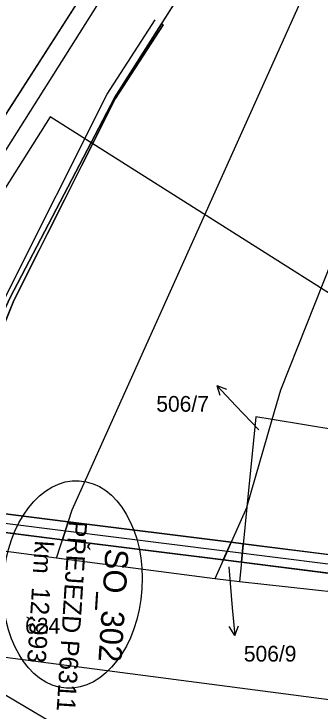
# Model space of a CAD drawing. Extents: x -746176 to -739709, y -1128407 to -1124482.
# Drawn here: x -743147.3 to -743114.2, y -1127113.5 to -1127038.1 of the extents above; entities that cross this region are included whole.
import ezdxf

# ---------------------------------------------------------------- set-up
doc = ezdxf.new("R2010")
doc.units = 0
for name, color, linetype in [('Vrstva 18', 7, 'Continuous'), ('Vrstva 21', 7, 'Continuous'), ('Vrstva 23', 7, 'Continuous'), ('Vrstva 29', 7, 'Continuous'), ('Vrstva 30', 7, 'Continuous'), ('Vrstva 31', 7, 'Continuous'), ('Vrstva 32', 7, 'Continuous'), ('Vrstva 33', 7, 'Continuous'), ('Vrstva 42', 7, 'Continuous'), ('Vrstva 43', 7, 'Continuous'), ('Vrstva 5', 7, 'Continuous'), ('Vrstva 6', 7, 'Continuous')]:
    doc.layers.add(name, color=color, linetype=linetype)

msp = doc.modelspace()

# ---------------------------------------------------------------- linework, layer by layer
at = {"layer": 'Vrstva 18'}
msp.add_lwpolyline([(-743072.487, -1126932.751), (-743098.647, -1126974.146), (-743125.94, -1127017.384), (-743152.604, -1127059.608), (-743175.023, -1127095.116), (-743199.163, -1127133.346), (-743215.971, -1127159.941), (-743232.818, -1127186.515), (-743247.456, -1127209.811), (-743254.52, -1127221.639), (-743261.299, -1127233.691), (-743264.155, -1127239.195), (-743264.862, -1127241.108), (-743267.337, -1127245.816), (-743268.289, -1127247.159), (-743271.711, -1127253.75), (-743281.122, -1127274.196), (-743291.923, -1127301.42), (-743296.724, -1127315.222), (-743301.116, -1127329.128), (-743306.787, -1127349.506)], dxfattribs=at)
at = {"layer": 'Vrstva 21'}
for p, q in [((-743136.47, -1127047.12), (-743131.381, -1127039.118)), ((-743131.226, -1127039.217), (-743136.391, -1127047.252)), ((-743131.381, -1127039.118), (-743131.226, -1127039.217)), ((-743147.78, -1127068.8), (-743136.47, -1127047.12)), ((-743136.391, -1127047.252), (-743147.347, -1127069.067)), ((-743147.347, -1127069.067), (-743151.792, -1127079.926)), ((-743149.573, -1127092.002), (-743141.471, -1127093.022)), ((-743141.471, -1127093.022), (-743142.103, -1127094.958)), ((-743141.471, -1127093.022), (-743123.858, -1127095.239)), ((-743142.103, -1127094.958), (-743150.442, -1127093.908)), ((-743124.702, -1127097.149), (-743142.103, -1127094.958)), ((-743123.858, -1127095.239), (-743124.702, -1127097.149)), ((-743123.858, -1127095.239), (-743122.548, -1127095.404)), ((-743122.548, -1127095.404), (-743122.742, -1127097.395)), ((-743122.548, -1127095.404), (-743105.198, -1127097.588)), ((-743122.742, -1127097.395), (-743124.702, -1127097.149)), ((-743105.47, -1127099.57), (-743122.742, -1127097.395))]:
    msp.add_line(p, q, dxfattribs=at)
at = {"layer": 'Vrstva 23'}
for points in [[(-743153.07, -1127080.408), (-743148.258, -1127068.653), (-743137.261, -1127046.755), (-743132.067, -1127038.676)], [(-743154.255, -1127082.611), (-743159.254, -1127091.791), (-743078.983, -1127101.896), (-743017.042, -1127110.608), (-742993.931, -1127114.824), (-742964.817, -1127120.763), (-742937.743, -1127126.541), (-742940.646, -1127140.696), (-742942.997, -1127146.397)]]:
    msp.add_lwpolyline(points, dxfattribs=at)
at = {"layer": 'Vrstva 29'}
msp.add_lwpolyline([(-743143.427, -1127049.192), (-743169.53, -1127090.542)], dxfattribs=at)
at = {"layer": 'Vrstva 30'}
for p, q in [((-743085.997, -1127085.593), (-743143.427, -1127049.192)), ((-743129.509, -1127122.8), (-743175.485, -1127095.847))]:
    msp.add_line(p, q, dxfattribs=at)
at = {"layer": 'Vrstva 31'}
msp.add_ellipse((-743140.999, -1127099.794), major_axis=(0.716, 11.227), ratio=0.666667, dxfattribs=at)
at = {"layer": 'Vrstva 33'}
for p, q in [((-743122.16, -1127091.42), (-743119.42, -1127081.96)), ((-743100.51, -1127085.04), (-743119.42, -1127081.96)), ((-743122.16, -1127091.42), (-743125.61, -1127099.18)), ((-743122.16, -1127091.42), (-743122.95, -1127099.53)), ((-743125.61, -1127099.18), (-743142.75, -1127096.94)), ((-743122.95, -1127099.53), (-743125.61, -1127099.18)), ((-743105.44, -1127101.41), (-743122.95, -1127099.53)), ((-743171.62, -1127104.6), (-743100.85, -1127113.88))]:
    msp.add_line(p, q, dxfattribs=at)
for points in [[(-743080.97, -1126930.41), (-743108.67, -1126985.4), (-743124.8, -1127012.28), (-743175.35, -1127091.16), (-743178.51, -1127091.81)], [(-743119.42, -1127081.96), (-743118.49, -1127078.74), (-743112.93, -1127064.74), (-743067.57, -1126961.77), (-743055.18, -1126936.67)], [(-743159.64, -1127094.74), (-743147.78, -1127068.8), (-743136.47, -1127047.12), (-743093.1, -1126978.92), (-743082.27, -1126962.07)], [(-743142.75, -1127096.94), (-743141.05, -1127091.73), (-743109, -1127020.35), (-743082.27, -1126962.07)], [(-743119.42, -1127081.96), (-743121.21, -1127081.67), (-743122.16, -1127091.42)], [(-743142.75, -1127096.94), (-743159.38, -1127094.77), (-743159.64, -1127094.74)]]:
    msp.add_lwpolyline(points, dxfattribs=at)
at = {"layer": 'Vrstva 43'}
for p, q in [((-743123.35, -1127080.45), (-743125.397, -1127078.255)), ((-743125.397, -1127078.255), (-743124.347, -1127078.646)), ((-743125.397, -1127078.255), (-743125.08, -1127079.329)), ((-743120.87, -1127083.07), (-743123.35, -1127080.45)), ((-743124.1, -1127097.89), (-743123.74, -1127102.32)), ((-743123.74, -1127102.32), (-743123.478, -1127105.31)), ((-743123.478, -1127105.31), (-743124.065, -1127104.356)), ((-743123.478, -1127105.31), (-743123.067, -1127104.268))]:
    msp.add_line(p, q, dxfattribs=at)
at = {"layer": 'Vrstva 5'}
msp.add_lwpolyline([(-743094.82, -1126957.905), (-743108.67, -1126985.4), (-743116.735, -1126998.84), (-743124.8, -1127012.28), (-743150.075, -1127051.72), (-743175.35, -1127091.16), (-743176.93, -1127091.485), (-743178.51, -1127091.81), (-743180.08, -1127092.14), (-743180.17, -1127093.19), (-743178.295, -1127093.33), (-743176.42, -1127093.47), (-743166.78, -1127095.57), (-743163.475, -1127095.74), (-743160.17, -1127095.91), (-743159.64, -1127094.74), (-743153.71, -1127081.77), (-743147.78, -1127068.8), (-743136.47, -1127047.12), (-743114.785, -1127013.02), (-743087.685, -1126970.495), (-743082.27, -1126962.07), (-743073.035, -1126947.525)], dxfattribs=at)
at = {"layer": 'Vrstva 6'}
for points in [[(-743131.226, -1127039.217), (-743131.381, -1127039.118), (-743136.47, -1127047.12), (-743147.78, -1127068.8), (-743152.668, -1127079.491), (-743151.792, -1127079.926), (-743147.347, -1127069.067), (-743141.869, -1127058.159), (-743136.391, -1127047.252)], [(-743154.54, -1127083.586), (-743158.78, -1127092.858), (-743142.103, -1127094.958), (-743141.471, -1127093.022), (-743157.675, -1127090.982), (-743153.837, -1127083.934)], [(-743141.471, -1127093.022), (-743142.103, -1127094.958), (-743124.707, -1127097.148), (-743123.858, -1127095.239)], [(-743123.858, -1127095.239), (-743124.707, -1127097.148), (-743122.742, -1127097.395), (-743122.548, -1127095.404)], [(-743122.548, -1127095.404), (-743122.742, -1127097.395), (-743105.47, -1127099.57), (-743105.49, -1127098.37), (-743105.198, -1127097.588)]]:
    msp.add_lwpolyline(points, close=True, dxfattribs=at)

# ---------------------------------------------------------------- texts
at = {"layer": 'Vrstva 32'}
for s, height, p in [('PŘEJEZD P6311', 2, (-743141.419, -1127092.843)), ('km  12,993', 2, (-743145.073, -1127095.022)), ('SO_302', 2.5, (-743137.44, -1127095.871))]:
    msp.add_text(s, height=height, rotation=266.35277, dxfattribs=at).set_placement(p)
at = {"layer": 'Vrstva 42'}
for s, p in [('506/7', (-743131.956, -1127081.103)), ('624', (-743146.144, -1127105.12)), ('506/9', (-743122.49, -1127108.143))]:
    msp.add_text(s, height=1.7, dxfattribs=at).set_placement(p)

doc.saveas('drawing.dxf')
